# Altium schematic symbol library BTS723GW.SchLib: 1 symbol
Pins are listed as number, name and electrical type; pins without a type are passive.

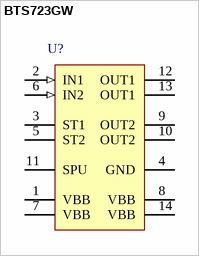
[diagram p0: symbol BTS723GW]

## BTS723GW
designator U?
Smart High-Side Power Switch, 2 Channels, 2 A Load Current, -40 to 150 degC, PG-DSO-14-37, Reel, Green; Manufacturer: Infineon; PartNumber: BTS723GW; Channels: 2; Green: TRUE; Group: Automotive Qualified; Load Current (typ): 2 A; Ptot (max): 3 W; Recommended Operating Voltage Max.: 58 V; Recommended Operating Voltage Min.: 7 V; RON @ 25degreesC: 105 mOhm; RON(max) @ 150degreesC: 210 mOhm; toff (max): 95 us; ton (max): 55 us
footprint INF-PG-DSO-14-37_N (SOP, 14-Leads, Body 8.65x3.9mm, Pitch 1.27mm, IPC Medium Density)
footprint INF-PG-DSO-14-37_L (SOP, 14-Leads, Body 8.65x3.9mm, Pitch 1.27mm, IPC High Density)
footprint INF-PG-DSO-14-37_M (SOP, 14-Leads, Body 8.65x3.9mm, Pitch 1.27mm, IPC Low Density)
pins: 1 VBB (power) "Positive power supply voltage. Design the wiring for the simultaneous max. short circuit currents from channel 1 to 2 and also for low thermal resistance", 2 IN1 (in) "Input 1,2 activates channel 1,2 in case of logic high signal", 3 ST1 (oc) "Diagnostic feedback 1,2 of channel 1,2 open drain", 4 GND (power) "Logic Ground", 5 ST2 (oc) "Diagnostic feedback 1,2 of channel 1,2 open drain", 6 IN2 (in) "Input 1,2 activates channel 1,2 in case of logic high signal", 7 VBB (power) "Positive power supply voltage. Design the wiring for the simultaneous max. short circuit currents from channel 1 to 2 and also for low thermal resistance", 8 VBB (power) "Positive power supply voltage. Design the wiring for the simultaneous max. short circuit currents from channel 1 to 2 and also for low thermal resistance", 9 OUT2 (power) "Output 1,2 protected high-side power output of channel 1,2. Design the wiring for the max. short circuit current; both output pins have to be connected in parallel for operation according this spec.", 10 OUT2 (power) "Output 1,2 protected high-side power output of channel 1,2. Design the wiring for the max. short circuit current; both output pins have to be connected in parallel for operation according this spec.", 11 SPU (power) "Connection for external pull up voltage source for the open drain status output. Pull up resistors are integrated.", 12 OUT1 (power) "Output 1,2 protected high-side power output of channel 1,2. Design the wiring for the max. short circuit current; both output pins have to be connected in parallel for operation according this spec.", 13 OUT1 (power) "Output 1,2 protected high-side power output of channel 1,2. Design the wiring for the max. short circuit current; both output pins have to be connected in parallel for operation according this spec.", 14 VBB (power) "Positive power supply voltage. Design the wiring for the simultaneous max. short circuit currents from channel 1 to 2 and also for low thermal resistance"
